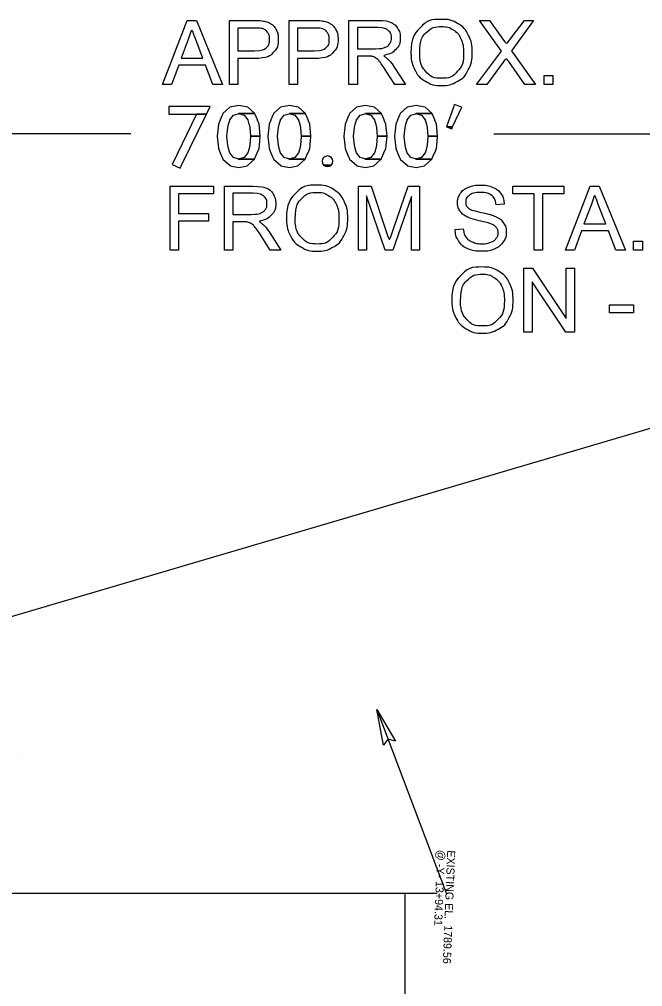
# Model space of a CAD drawing. Extents: x 557583 to 560285, y 513145 to 516544.
# Drawn here: x 559657.8 to 559852.4, y 515428.4 to 515730.6 of the extents above; entities that cross this region are included whole.
import ezdxf

# ---------------------------------------------------------------- set-up
doc = ezdxf.new("R2010")
doc.units = 0
for name, color, linetype in [('Default', 7, 'Continuous'), ('Prop Superelevation Label', 7, 'Continuous'), ('Scratch_Level_0', 7, 'Continuous'), ('Scratch_Level_3', 7, 'Continuous'), ('Scratch_Level_4', 7, 'Continuous')]:
    doc.layers.add(name, color=color, linetype=linetype)

msp = doc.modelspace()

# ---------------------------------------------------------------- linework, layer by layer
at = {"layer": 'Default'}
for p, q in [((559692.61, 515694.81), (559399.28, 515694.81)), ((559805.95, 515694.81), (560099.28, 515694.81)), ((559409.28, 515457.65), (559788.26, 515457.65)), ((559778.26, 514977.65), (559778.26, 515457.65))]:
    msp.add_line(p, q, dxfattribs=at)
for points in [[(559742.05, 515710.23), (559742.05, 515730.23), (559749.59, 515730.23)], [(559749.82, 515727.87), (559744.7, 515727.87), (559744.7, 515720.72)], [(559744.7, 515720.72), (559749.87, 515720.72)], [(559749.83, 515718.36), (559744.7, 515718.36), (559744.7, 515710.23), (559742.05, 515710.23)]]:
    msp.add_lwpolyline(points, dxfattribs=at)
for points in [[(559749.59, 515730.23), (559751.59, 515730.23), (559752.64, 515730.04), (559754.11, 515729.79), (559755.11, 515729.11), (559756.11, 515728.42), (559756.71, 515727.17), (559757.32, 515725.93), (559757.32, 515724.44), (559757.32, 515721.89), (559755.7, 515720.12), (559754.07, 515718.36), (559749.83, 515718.36)], [(559749.87, 515720.72), (559752.44, 515720.72), (559753.51, 515721.67), (559754.59, 515722.63), (559754.59, 515724.36), (559754.59, 515725.62), (559753.96, 515726.51), (559753.32, 515727.4), (559752.29, 515727.69), (559751.62, 515727.87), (559749.82, 515727.87)]]:
    msp.add_open_spline(points, degree=3, dxfattribs=at)
at = {"layer": 'Prop Superelevation Label'}
msp.add_line((559658.96, 515499.52), (559658.96, 515499.52), dxfattribs=at)
at = {"layer": 'Scratch_Level_0'}
for points in [[(559702.58, 515710.23), (559710.26, 515730.23), (559713.13, 515730.23), (559721.3, 515710.23), (559718.28, 515710.23), (559715.96, 515716.28), (559707.58, 515716.28), (559705.38, 515710.23), (559702.58, 515710.23)], [(559723.4, 515710.23), (559723.4, 515730.23), (559730.95, 515730.23)], [(559731.17, 515727.87), (559726.05, 515727.87), (559726.05, 515720.72)], [(559760.73, 515710.23), (559760.73, 515730.23), (559769.61, 515730.23)], [(559769.72, 515728.02), (559763.39, 515728.02), (559763.39, 515721.41)], [(559800.58, 515710.23), (559808.32, 515720.6), (559801.5, 515730.23), (559804.64, 515730.23), (559808.29, 515725.11)], [(559811.49, 515724.91), (559815.5, 515730.23), (559818.37, 515730.23), (559811.43, 515720.73), (559818.92, 515710.23), (559815.67, 515710.23), (559810.61, 515717.37)], [(559710.55, 515724.31), (559708.34, 515718.43)], [(559708.34, 515718.43), (559715.13, 515718.43), (559713.04, 515723.99)], [(559726.05, 515720.72), (559731.23, 515720.72)], [(559766.46, 515719.12), (559763.39, 515719.12), (559763.39, 515710.23), (559760.73, 515710.23)], [(559763.39, 515721.41), (559769.07, 515721.41)], [(559731.19, 515718.36), (559726.05, 515718.36), (559726.05, 515710.23), (559723.4, 515710.23)], [(559808.83, 515717.17), (559803.76, 515710.23), (559800.58, 515710.23)], [(559774.88, 515715.68), (559778.34, 515710.23), (559775.03, 515710.23), (559772.39, 515714.39)], [(559821.63, 515710.23), (559821.63, 515713.02), (559824.42, 515713.02), (559824.42, 515710.23), (559821.63, 515710.23)], [(559704.9, 515658.46), (559704.9, 515678.46), (559718.4, 515678.46), (559718.4, 515676.1), (559707.55, 515676.1), (559707.55, 515669.91), (559716.94, 515669.91), (559716.94, 515667.55), (559707.55, 515667.55), (559707.55, 515658.46), (559704.9, 515658.46)], [(559721.88, 515658.46), (559721.88, 515678.46), (559730.75, 515678.46)], [(559763.68, 515658.46), (559763.68, 515678.46), (559767.66, 515678.46), (559772.39, 515664.3)], [(559774.42, 515664.55), (559779.22, 515678.46), (559782.78, 515678.46), (559782.78, 515658.46), (559780.23, 515658.46), (559780.23, 515675.2), (559774.4, 515658.46), (559772.01, 515658.46), (559766.22, 515675.49), (559766.22, 515658.46), (559763.68, 515658.46)], [(559818.52, 515658.46), (559818.52, 515676.1), (559811.94, 515676.1), (559811.94, 515678.46), (559827.79, 515678.46), (559827.79, 515676.1), (559821.18, 515676.1), (559821.18, 515658.46), (559818.52, 515658.46)], [(559828.32, 515658.46), (559836.01, 515678.46), (559838.87, 515678.46), (559847.04, 515658.46), (559844.03, 515658.46), (559841.71, 515664.51), (559833.32, 515664.51), (559831.13, 515658.46), (559828.32, 515658.46)], [(559730.86, 515676.25), (559724.53, 515676.25), (559724.53, 515669.64)], [(559809.23, 515672.84), (559806.69, 515672.64)], [(559836.3, 515672.54), (559834.09, 515666.66)], [(559834.09, 515666.66), (559840.88, 515666.66), (559838.78, 515672.22)], [(559724.53, 515669.64), (559730.22, 515669.64)], [(559727.6, 515667.35), (559724.53, 515667.35), (559724.53, 515658.46), (559721.88, 515658.46)], [(559793.89, 515664.9), (559796.39, 515665.11)], [(559736.02, 515663.91), (559739.48, 515658.46), (559736.18, 515658.46), (559733.53, 515662.62)], [(559849.53, 515658.46), (559849.53, 515661.25), (559852.32, 515661.25), (559852.32, 515658.46), (559849.53, 515658.46)], [(559815.35, 515632.87), (559815.35, 515652.87), (559818.06, 515652.87), (559828.58, 515637.17), (559828.58, 515652.87), (559831.11, 515652.87), (559831.11, 515632.87), (559828.4, 515632.87), (559817.88, 515648.58), (559817.88, 515632.87), (559815.35, 515632.87)], [(559842.03, 515638.88), (559842.03, 515641.35), (559849.59, 515641.35), (559849.59, 515638.88), (559842.03, 515638.88)]]:
    msp.add_lwpolyline(points, dxfattribs=at)
for points in [[(559723.67, 515684.87), (559726.33, 515684.33), (559728.92, 515684.87), (559729.07, 515684.9), (559731.28, 515686.93), (559726.29, 515686.93), (559726.16, 515686.96), (559726.09, 515686.98), (559724.7, 515687.38), (559723.54, 515688.88), (559723.53, 515688.9), (559723.53, 515688.9), (559723.16, 515690.24), (559723.16, 515690.27), (559722.89, 515691.24), (559722.88, 515691.3), (559722.64, 515693.99), (559722.64, 515694.02), (559722.64, 515694.05), (559722.88, 515696.75), (559723.15, 515697.77), (559723.16, 515697.8), (559723.51, 515699.11), (559723.52, 515699.15), (559724.7, 515700.67), (559726.2, 515701.07), (559726.25, 515701.08), (559726.39, 515701.12), (559731.32, 515701.12), (559729.15, 515703.11), (559729.04, 515703.13), (559726.36, 515703.72), (559726.36, 515703.72), (559723.58, 515703.13), (559723.56, 515703.11), (559721.41, 515701.12), (559721.37, 515701.08), (559721.35, 515701.07), (559721.19, 515700.67), (559720.56, 515699.15), (559720.55, 515699.11), (559720.01, 515697.8), (559720, 515697.77), (559719.9, 515696.75), (559719.61, 515694.05), (559719.61, 515694.02), (559719.61, 515693.99), (559719.88, 515691.3), (559719.89, 515691.24), (559719.99, 515690.27), (559719.99, 515690.24), (559720.54, 515688.9), (559720.55, 515688.88), (559721.16, 515687.38), (559721.32, 515686.98), (559721.33, 515686.96), (559721.37, 515686.93), (559723.63, 515684.9)], [(559739.49, 515684.87), (559742.15, 515684.33), (559744.74, 515684.87), (559744.89, 515684.9), (559747.09, 515686.93), (559742.11, 515686.93), (559741.98, 515686.96), (559741.91, 515686.98), (559740.52, 515687.38), (559739.35, 515688.88), (559739.35, 515688.9), (559739.35, 515688.9), (559738.98, 515690.24), (559738.98, 515690.27), (559738.71, 515691.24), (559738.69, 515691.3), (559738.46, 515693.99), (559738.46, 515694.02), (559738.46, 515694.05), (559738.69, 515696.75), (559738.97, 515697.77), (559738.98, 515697.8), (559739.33, 515699.11), (559739.34, 515699.15), (559740.52, 515700.67), (559742.02, 515701.07), (559742.07, 515701.08), (559742.21, 515701.12), (559747.14, 515701.12), (559744.97, 515703.11), (559744.85, 515703.13), (559742.18, 515703.72), (559742.18, 515703.72), (559739.4, 515703.13), (559739.38, 515703.11), (559737.22, 515701.12), (559737.18, 515701.08), (559737.17, 515701.07), (559737.01, 515700.67), (559736.38, 515699.15), (559736.36, 515699.11), (559735.83, 515697.8), (559735.82, 515697.77), (559735.72, 515696.75), (559735.43, 515694.05), (559735.43, 515694.02), (559735.43, 515693.99), (559735.7, 515691.3), (559735.71, 515691.24), (559735.81, 515690.27), (559735.81, 515690.24), (559736.36, 515688.9), (559736.36, 515688.88), (559736.98, 515687.38), (559737.14, 515686.98), (559737.15, 515686.96), (559737.19, 515686.93), (559739.45, 515684.9)], [(559763.22, 515684.87), (559765.88, 515684.33), (559768.47, 515684.87), (559768.62, 515684.9), (559770.82, 515686.93), (559765.83, 515686.93), (559765.7, 515686.96), (559765.64, 515686.98), (559764.25, 515687.38), (559763.08, 515688.88), (559763.08, 515688.9), (559763.08, 515688.9), (559762.71, 515690.24), (559762.7, 515690.27), (559762.44, 515691.24), (559762.42, 515691.3), (559762.18, 515693.99), (559762.18, 515694.02), (559762.19, 515694.05), (559762.42, 515696.75), (559762.7, 515697.77), (559762.7, 515697.8), (559763.06, 515699.11), (559763.07, 515699.15), (559764.25, 515700.67), (559765.75, 515701.07), (559765.8, 515701.08), (559765.94, 515701.12), (559770.87, 515701.12), (559768.69, 515703.11), (559768.58, 515703.13), (559765.91, 515703.72), (559765.9, 515703.72), (559763.13, 515703.13), (559763.1, 515703.11), (559760.95, 515701.12), (559760.91, 515701.08), (559760.9, 515701.07), (559760.74, 515700.67), (559760.11, 515699.15), (559760.09, 515699.11), (559759.55, 515697.8), (559759.55, 515697.77), (559759.44, 515696.75), (559759.16, 515694.05), (559759.15, 515694.02), (559759.16, 515693.99), (559759.43, 515691.3), (559759.43, 515691.24), (559759.53, 515690.27), (559759.54, 515690.24), (559760.08, 515688.9), (559760.09, 515688.88), (559760.71, 515687.38), (559760.87, 515686.98), (559760.88, 515686.96), (559760.92, 515686.93), (559763.18, 515684.9)], [(559779.03, 515684.87), (559781.69, 515684.33), (559784.29, 515684.87), (559784.43, 515684.9), (559786.64, 515686.93), (559781.65, 515686.93), (559781.52, 515686.96), (559781.46, 515686.98), (559780.06, 515687.38), (559778.9, 515688.88), (559778.9, 515688.9), (559778.89, 515688.9), (559778.53, 515690.24), (559778.52, 515690.27), (559778.25, 515691.24), (559778.24, 515691.3), (559778, 515693.99), (559778, 515694.02), (559778.01, 515694.05), (559778.24, 515696.75), (559778.52, 515697.77), (559778.52, 515697.8), (559778.88, 515699.11), (559778.89, 515699.15), (559780.06, 515700.67), (559781.57, 515701.07), (559781.62, 515701.08), (559781.75, 515701.12), (559786.69, 515701.12), (559784.51, 515703.11), (559784.4, 515703.13), (559781.72, 515703.72), (559781.72, 515703.72), (559778.95, 515703.13), (559778.92, 515703.11), (559776.77, 515701.12), (559776.73, 515701.08), (559776.72, 515701.07), (559776.55, 515700.67), (559775.93, 515699.15), (559775.91, 515699.11), (559775.37, 515697.8), (559775.37, 515697.77), (559775.26, 515696.75), (559774.98, 515694.05), (559774.97, 515694.02), (559774.98, 515693.99), (559775.25, 515691.3), (559775.25, 515691.24), (559775.35, 515690.27), (559775.35, 515690.24), (559775.9, 515688.9), (559775.91, 515688.88), (559776.52, 515687.38), (559776.68, 515686.98), (559776.69, 515686.96), (559776.73, 515686.93), (559779, 515684.9)], [(559793.33, 515703.19), (559791.17, 515697), (559793.07, 515697), (559795.95, 515703.19), (559793.6, 515703.96)], [(559704.52, 515703.36), (559704.52, 515700.93), (559716.24, 515700.93), (559717.42, 515703.36)], [(559705.55, 515685.21), (559708.02, 515684.1), (559708.56, 515685.21), (559716.24, 515700.93), (559713.19, 515700.93)], [(559729.82, 515696.75), (559730.03, 515694.05), (559733.06, 515694.05), (559732.8, 515696.75), (559732.7, 515697.77), (559732.69, 515697.8), (559732.68, 515697.8), (559732.16, 515699.11), (559732.16, 515699.11), (559732.14, 515699.15), (559731.53, 515700.67), (559731.53, 515700.67), (559731.37, 515701.07), (559731.37, 515701.08), (559731.32, 515701.12), (559726.39, 515701.12), (559726.52, 515701.08), (559726.56, 515701.07), (559727.98, 515700.67), (559729.15, 515699.15), (559729.18, 515699.11), (559729.53, 515697.8), (559729.54, 515697.77)], [(559745.63, 515696.75), (559745.85, 515694.05), (559748.88, 515694.05), (559748.62, 515696.75), (559748.52, 515697.77), (559748.51, 515697.8), (559748.5, 515697.8), (559747.98, 515699.11), (559747.98, 515699.11), (559747.96, 515699.15), (559747.35, 515700.67), (559747.35, 515700.67), (559747.19, 515701.07), (559747.18, 515701.08), (559747.14, 515701.12), (559742.21, 515701.12), (559742.34, 515701.08), (559742.38, 515701.07), (559743.8, 515700.67), (559744.97, 515699.15), (559745, 515699.11), (559745.35, 515697.8), (559745.36, 515697.77)], [(559769.36, 515696.75), (559769.58, 515694.05), (559772.61, 515694.05), (559772.34, 515696.75), (559772.25, 515697.77), (559772.23, 515697.8), (559772.23, 515697.8), (559771.71, 515699.11), (559771.7, 515699.11), (559771.69, 515699.15), (559771.08, 515700.67), (559771.07, 515700.67), (559770.92, 515701.07), (559770.91, 515701.08), (559770.87, 515701.12), (559765.94, 515701.12), (559766.07, 515701.08), (559766.11, 515701.07), (559767.53, 515700.67), (559768.7, 515699.15), (559768.73, 515699.11), (559769.08, 515697.8), (559769.08, 515697.77)], [(559785.18, 515696.75), (559785.4, 515694.05), (559788.42, 515694.05), (559788.16, 515696.75), (559788.06, 515697.77), (559788.05, 515697.8), (559788.05, 515697.8), (559787.52, 515699.11), (559787.52, 515699.11), (559787.51, 515699.15), (559786.89, 515700.67), (559786.89, 515700.67), (559786.73, 515701.07), (559786.73, 515701.08), (559786.69, 515701.12), (559781.75, 515701.12), (559781.88, 515701.08), (559781.93, 515701.07), (559783.35, 515700.67), (559784.52, 515699.15), (559784.55, 515699.11), (559784.9, 515697.8), (559784.9, 515697.77)], [(559791.17, 515697), (559792.8, 515696.42), (559793.07, 515697)], [(559726.42, 515686.96), (559726.29, 515686.93), (559731.28, 515686.93), (559731.32, 515686.96), (559731.34, 515686.98), (559731.5, 515687.38), (559732.12, 515688.88), (559732.13, 515688.9), (559732.68, 515690.24), (559732.69, 515690.27), (559732.79, 515691.24), (559732.79, 515691.3), (559733.06, 515693.99), (559733.06, 515694.02), (559733.06, 515694.05), (559730.03, 515694.05), (559730.03, 515694.02), (559730.03, 515693.99), (559729.81, 515691.3), (559729.81, 515691.24), (559729.55, 515690.27), (559729.54, 515690.24), (559729.18, 515688.9), (559729.17, 515688.88), (559727.98, 515687.38), (559726.49, 515686.98)], [(559742.24, 515686.96), (559742.11, 515686.93), (559747.09, 515686.93), (559747.13, 515686.96), (559747.15, 515686.98), (559747.32, 515687.38), (559747.94, 515688.88), (559747.95, 515688.9), (559748.5, 515690.24), (559748.51, 515690.27), (559748.61, 515691.24), (559748.61, 515691.3), (559748.88, 515693.99), (559748.88, 515694.02), (559748.88, 515694.05), (559745.85, 515694.05), (559745.85, 515694.02), (559745.85, 515693.99), (559745.63, 515691.3), (559745.63, 515691.24), (559745.36, 515690.27), (559745.36, 515690.24), (559745, 515688.9), (559744.98, 515688.88), (559743.8, 515687.38), (559742.31, 515686.98)], [(559765.97, 515686.96), (559765.83, 515686.93), (559770.82, 515686.93), (559770.86, 515686.96), (559770.88, 515686.98), (559771.04, 515687.38), (559771.67, 515688.88), (559771.67, 515688.9), (559772.23, 515690.24), (559772.24, 515690.27), (559772.33, 515691.24), (559772.34, 515691.3), (559772.61, 515693.99), (559772.61, 515694.02), (559772.61, 515694.05), (559769.58, 515694.05), (559769.58, 515694.02), (559769.57, 515693.99), (559769.36, 515691.3), (559769.35, 515691.24), (559769.09, 515690.27), (559769.08, 515690.24), (559768.72, 515688.9), (559768.71, 515688.88), (559767.53, 515687.38), (559766.04, 515686.98)], [(559781.79, 515686.96), (559781.65, 515686.93), (559786.64, 515686.93), (559786.68, 515686.96), (559786.7, 515686.98), (559786.86, 515687.38), (559787.48, 515688.88), (559787.49, 515688.9), (559788.05, 515690.24), (559788.06, 515690.27), (559788.15, 515691.24), (559788.16, 515691.3), (559788.42, 515693.99), (559788.43, 515694.02), (559788.42, 515694.05), (559785.39, 515694.05), (559785.39, 515694.02), (559785.39, 515693.99), (559785.18, 515691.3), (559785.17, 515691.24), (559784.91, 515690.27), (559784.9, 515690.24), (559784.54, 515688.9), (559784.53, 515688.88), (559783.35, 515687.38), (559781.86, 515686.98)], [(559752.47, 515685.6), (559752.83, 515685.06), (559755.2, 515685.06), (559755.56, 515685.6), (559755.69, 515686.24), (559755.56, 515686.88), (559755.2, 515687.42), (559754.66, 515687.78), (559754.02, 515687.9), (559753.37, 515687.78), (559752.83, 515687.42), (559752.47, 515686.88), (559752.34, 515686.24)], [(559753.37, 515684.69), (559754.02, 515684.57), (559754.66, 515684.69), (559755.2, 515685.06), (559752.83, 515685.06)]]:
    msp.add_lwpolyline(points, close=True, dxfattribs=at)
for points in [[(559730.95, 515730.23), (559732.94, 515730.23), (559733.99, 515730.04), (559735.47, 515729.79), (559736.47, 515729.11), (559737.46, 515728.42), (559738.07, 515727.17), (559738.68, 515725.93), (559738.68, 515724.44), (559738.68, 515721.89), (559737.05, 515720.12), (559735.43, 515718.36), (559731.19, 515718.36)], [(559731.23, 515720.72), (559733.79, 515720.72), (559734.87, 515721.67), (559735.95, 515722.63), (559735.95, 515724.36), (559735.95, 515725.62), (559735.31, 515726.51), (559734.68, 515727.4), (559733.64, 515727.69), (559732.97, 515727.87), (559731.17, 515727.87)], [(559769.07, 515721.41), (559770.89, 515721.41), (559771.91, 515721.78), (559772.93, 515722.16), (559773.46, 515722.98), (559774, 515723.81), (559774, 515724.77), (559774, 515726.19), (559772.97, 515727.11), (559771.94, 515728.02), (559769.72, 515728.02)], [(559769.61, 515730.23), (559772.28, 515730.23), (559773.67, 515729.69), (559775.06, 515729.15), (559775.89, 515727.79), (559776.73, 515726.43), (559776.73, 515724.77), (559776.73, 515722.65), (559775.35, 515721.19), (559773.97, 515719.73), (559771.09, 515719.33), (559772.14, 515718.83), (559772.69, 515718.34), (559773.85, 515717.27), (559774.88, 515715.68)], [(559780.08, 515719.97), (559780.08, 515724.95), (559782.75, 515727.77), (559785.43, 515730.58), (559789.66, 515730.58), (559792.43, 515730.58), (559794.65, 515729.26), (559796.88, 515727.94), (559798.04, 515725.57), (559799.21, 515723.2), (559799.21, 515720.2), (559799.21, 515717.16), (559797.98, 515714.76), (559796.75, 515712.36), (559794.5, 515711.13), (559792.25, 515709.9), (559789.64, 515709.9), (559786.82, 515709.9), (559784.6, 515711.26), (559782.37, 515712.62), (559781.23, 515714.98), (559780.08, 515717.34), (559780.08, 515719.97)], [(559782.81, 515719.94), (559782.81, 515716.33), (559784.75, 515714.25), (559786.7, 515712.17), (559789.63, 515712.17), (559792.62, 515712.17), (559794.55, 515714.27), (559796.48, 515716.37), (559796.48, 515720.23), (559796.48, 515722.67), (559795.66, 515724.49), (559794.83, 515726.31), (559793.24, 515727.31), (559791.65, 515728.31), (559789.67, 515728.31), (559786.86, 515728.31), (559784.83, 515726.38), (559782.81, 515724.45), (559782.81, 515719.94)], [(559713.04, 515723.99), (559712.1, 515726.51), (559711.63, 515728.13), (559711.23, 515726.21), (559710.55, 515724.31)], [(559808.29, 515725.11), (559809.43, 515723.52), (559809.9, 515722.65), (559810.57, 515723.73), (559811.49, 515724.91)], [(559772.39, 515714.39), (559771.23, 515716.19), (559770.48, 515717.15), (559769.73, 515718.1), (559769.14, 515718.49), (559768.54, 515718.87), (559767.93, 515719.02), (559767.48, 515719.12), (559766.46, 515719.12)], [(559810.61, 515717.37), (559810.18, 515717.98), (559809.78, 515718.6), (559809.12, 515717.57), (559808.83, 515717.17)], [(559730.75, 515678.46), (559733.42, 515678.46), (559734.81, 515677.92), (559736.2, 515677.39), (559737.04, 515676.02), (559737.87, 515674.66), (559737.87, 515673.01), (559737.87, 515670.88), (559736.49, 515669.42), (559735.11, 515667.96), (559732.24, 515667.56), (559733.29, 515667.06), (559733.83, 515666.57), (559734.99, 515665.5), (559736.02, 515663.91)], [(559741.22, 515668.2), (559741.22, 515673.18), (559743.9, 515676), (559746.57, 515678.81), (559750.8, 515678.81), (559753.57, 515678.81), (559755.8, 515677.49), (559758.02, 515676.17), (559759.19, 515673.8), (559760.35, 515671.44), (559760.35, 515668.44), (559760.35, 515665.4), (559759.13, 515663), (559757.9, 515660.6), (559755.65, 515659.36), (559753.39, 515658.13), (559750.79, 515658.13), (559747.96, 515658.13), (559745.74, 515659.49), (559743.51, 515660.85), (559742.37, 515663.21), (559741.22, 515665.57), (559741.22, 515668.2)], [(559743.95, 515668.17), (559743.95, 515664.56), (559745.9, 515662.48), (559747.84, 515660.4), (559750.77, 515660.4), (559753.76, 515660.4), (559755.69, 515662.5), (559757.62, 515664.6), (559757.62, 515668.46), (559757.62, 515670.9), (559756.8, 515672.72), (559755.97, 515674.54), (559754.38, 515675.54), (559752.79, 515676.54), (559750.82, 515676.54), (559748, 515676.54), (559745.98, 515674.61), (559743.95, 515672.68), (559743.95, 515668.17)], [(559806.69, 515672.64), (559806.49, 515674.54), (559805.3, 515675.51), (559804.12, 515676.48), (559801.8, 515676.48), (559799.39, 515676.48), (559798.29, 515675.6), (559797.18, 515674.72), (559797.18, 515673.48), (559797.18, 515672.4), (559797.96, 515671.7), (559798.73, 515671.01), (559801.97, 515670.27), (559805.21, 515669.54), (559806.41, 515669), (559808.16, 515668.19), (559808.99, 515666.96), (559809.82, 515665.72), (559809.82, 515664.12), (559809.82, 515662.52), (559808.91, 515661.11), (559807.99, 515659.7), (559806.28, 515658.91), (559804.56, 515658.13), (559802.42, 515658.13), (559799.71, 515658.13), (559797.87, 515658.92), (559796.03, 515659.71), (559794.99, 515661.3), (559793.94, 515662.89), (559793.89, 515664.9)], [(559796.39, 515665.11), (559796.57, 515663.61), (559797.22, 515662.64), (559797.86, 515661.68), (559799.23, 515661.08), (559800.6, 515660.49), (559802.3, 515660.49), (559803.82, 515660.49), (559804.98, 515660.94), (559806.14, 515661.39), (559806.71, 515662.18), (559807.27, 515662.96), (559807.27, 515663.89), (559807.27, 515664.83), (559806.73, 515665.54), (559806.19, 515666.24), (559804.93, 515666.72), (559804.12, 515667.03), (559801.35, 515667.69), (559798.58, 515668.36), (559797.48, 515668.94), (559796.04, 515669.69), (559795.34, 515670.81), (559794.64, 515671.92), (559794.64, 515673.3), (559794.64, 515674.81), (559795.5, 515676.13), (559796.36, 515677.45), (559798.01, 515678.13), (559799.67, 515678.81), (559801.69, 515678.81), (559803.92, 515678.81), (559805.62, 515678.1), (559807.32, 515677.38), (559808.24, 515675.99), (559809.16, 515674.6), (559809.23, 515672.84)], [(559730.22, 515669.64), (559732.03, 515669.64), (559733.05, 515670.01), (559734.08, 515670.39), (559734.61, 515671.21), (559735.14, 515672.04), (559735.14, 515673.01), (559735.14, 515674.42), (559734.11, 515675.34), (559733.08, 515676.25), (559730.86, 515676.25)], [(559838.78, 515672.22), (559837.84, 515674.75), (559837.37, 515676.36), (559836.98, 515674.44), (559836.3, 515672.54)], [(559733.53, 515662.62), (559732.37, 515664.43), (559731.62, 515665.38), (559730.87, 515666.34), (559730.28, 515666.72), (559729.69, 515667.1), (559729.07, 515667.25), (559728.62, 515667.35), (559727.6, 515667.35)], [(559772.39, 515664.3), (559773.05, 515662.32), (559773.35, 515661.34), (559773.69, 515662.43), (559774.42, 515664.55)], [(559792.83, 515642.61), (559792.83, 515647.59), (559795.51, 515650.41), (559798.18, 515653.22), (559802.41, 515653.22), (559805.18, 515653.22), (559807.41, 515651.9), (559809.63, 515650.58), (559810.8, 515648.21), (559811.96, 515645.85), (559811.96, 515642.85), (559811.96, 515639.81), (559810.74, 515637.41), (559809.51, 515635.01), (559807.26, 515633.77), (559805.01, 515632.54), (559802.4, 515632.54), (559799.57, 515632.54), (559797.35, 515633.9), (559795.13, 515635.27), (559793.98, 515637.62), (559792.83, 515639.98), (559792.83, 515642.61)], [(559795.56, 515642.58), (559795.56, 515638.97), (559797.51, 515636.89), (559799.45, 515634.81), (559802.39, 515634.81), (559805.37, 515634.81), (559807.3, 515636.91), (559809.24, 515639.01), (559809.24, 515642.87), (559809.24, 515645.31), (559808.41, 515647.13), (559807.58, 515648.95), (559805.99, 515649.95), (559804.4, 515650.95), (559802.43, 515650.95), (559799.61, 515650.95), (559797.59, 515649.02), (559795.56, 515647.09), (559795.56, 515642.58)]]:
    msp.add_open_spline(points, degree=3, dxfattribs=at)
at = {"layer": 'Scratch_Level_3'}
msp.add_line((559769.4, 515515.01), (559791.16, 515457.38), dxfattribs=at)
msp.add_lwpolyline([(559771.52, 515503.8), (559769.4, 515515.01), (559775.23, 515505.12), (559772.86, 515505.76)], close=True, dxfattribs=at)
at = {"layer": 'Scratch_Level_4'}
msp.add_line((559972.04, 515637.38), (559406.15, 515470.45), dxfattribs=at)

# ---------------------------------------------------------------- texts
at = {"layer": 'Scratch_Level_3'}
for s, p in [('@ -Y- 13+94.31', (559788.25, 515471.17)), ('EXISTING EL.  1789.56 ', (559791.42, 515471.05))]:
    msp.add_text(s, height=2.5, rotation=267.7628, dxfattribs=at).set_placement(p)

doc.saveas('drawing.dxf')
